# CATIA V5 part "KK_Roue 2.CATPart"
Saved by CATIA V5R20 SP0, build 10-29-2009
Part number: Roue 2
Bounding box of the stored display mesh (mm): x -704 to -256, y 176.046 to 1935.954, z -3951.98 to -2192.02
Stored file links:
  G:\Khaled_CFAO_2011\ST2M\ST2M_GR2\aboulegue\Khaled\CAD_thinkMOTION\KK_Roue 2.CATPart
  G:\Khaled_CFAO_2011\ST2M\ST2M_GR2\aboulegue\Khaled\CAD_thinkMOTION\KK_Train_Atterrissage.CATProduct
  G:\Khaled_CFAO_2011\ST2M\ST2M_GR2\aboulegue\Khaled\CAD_thinkMOTION\KK_Squelette_Roue_2.CATPart
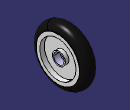
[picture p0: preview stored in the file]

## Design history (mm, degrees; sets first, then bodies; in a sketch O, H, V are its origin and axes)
Set1
  Plane1 "Plan roue 2": linked copy from another document
  Line1: linked copy from another document
  Line2: linked copy from another document
  Point1: linked copy from another document
  Point2: linked copy from another document
Body1 (main body)
  Sketch1 on Plane1, origin (0, 1056, 0), H (1, 0, 0), V (0, 0, 1)
    line L1 (-672, -3072) -> (-672, -2872)
    line L2 (-672, -2872) -> (-560, -2872)
    line L3 (-560, -2872) -> (-560, -2512)
    line L4 (-560, -2512) -> (-704, -2512)
    line L5 (-704, -2512) -> (-704, -2400)
    line L6 (-704, -2400) -> (-688, -2400)
    line L7 (-688, -2400) -> (-688, -2496)
    line L8 (-688, -2496) -> (-272, -2496)
    line L9 (-272, -2496) -> (-272, -2400)
    point P10 (-272, -2400)
    line L10 (-272, -2400) -> (-256, -2400)
    line L11 (-256, -2400) -> (-256, -2512)
    point P12 (-256, -2512)
    line L12 (-256, -2512) -> (-400, -2512)
    line L13 (-400, -2512) -> (-400, -2872)
    point P14 (-400, -2872)
    line L14 (-400, -2872) -> (-288, -2872)
    line L15 (-288, -2872) -> (-288, -3072)
    line L16 (-288, -3072) -> (-672, -3072)
    reference projected line E1 (-680, -3072) -> (-280, -3072) from Line1
    reference projected line E2 (-480, -3072) -> (-480, -2400) from Line2
    reference projected line E3 (-480, -3072) -> (-480, -2400) from Line2
    length L16 = 384
    length L14 = 112
    length L2 = 112
    distance L3 E2 = 80
    length L12 = 144
    length L4 = 144
    length L9 = 96
    length L5 = 112
    length L8 = 416
    distance L7 E3 = 208
    distance L16 L10 = 672
    length L15 = 200
    vertical: L1 V, L3 V, L5 V, L7 V, L9 V, L11 V, L13 V, L15 V
    horizontal: L2 H, L4 H, L6 H, L8 H, L10 H, L12 H, L14 H, L16 H
    coincidence: P10 L6, P12 L4, P14 L2, L16 E1
  Shaft1: profile Sketch1, axis Line1, angle 360
  Sketch2 on Plane1, origin (0, 1056, 0), H (1, 0, 0), V (0, 0, 1)
  Sketch3 on Plane1, origin (0, 1056, 0), H (1, 0, 0), V (0, 0, 1)
    arc A1 centre (-480, -2400) radius 208 from (-272, -2400) to (-688, -2400) ccw
    point P1 (-480, -2400)
    reference projected point E1 (-480, -2400) from Point1
    line L1 (-688, -2400) -> (-272, -2400)
    radius A1 = 208
    length L1 = 416
    coincidence: P1 E1
    horizontal: L1 H
  Shaft2: profile Sketch3, axis Line1, angle 360
  Sketch4 on face of Shaft1 from Sketch1.L15, origin (-288, 0, 0), H (0, 1, 0), V (0, 0, 1)
    circle A1 centre (1056, -3072) radius 160
    point P1 (1056, -3072)
    reference projected point E1 (1056, -3072) from Point2
    radius A1 = 160
    coincidence: P1 E1
  Pocket1: profile Sketch4, direction (-1, 0, 0), length 192
  Fillet1: radius 25, on edge [face of Shaft1 from Sketch1.L1 | face of Shaft1 from Sketch1.L2]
